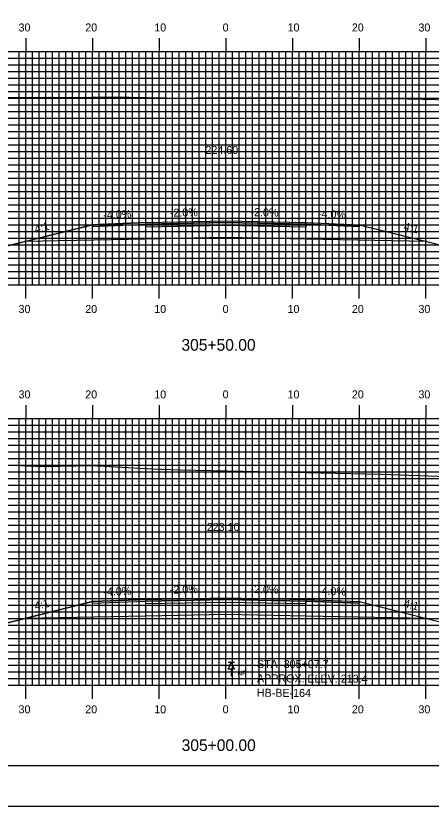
# Model space of a CAD drawing. Extents: x 1816883 to 1817226, y 442591 to 442811.
# Drawn here: x 1817017.1 to 1817079.4, y 442590.5 to 442709 of the extents above; entities that cross this region are included whole.
import ezdxf

# ---------------------------------------------------------------- set-up
doc = ezdxf.new("R2010")
doc.units = 0
for name, color, linetype in [('ANNOTATION', 7, 'Continuous'), ('BORDER', 7, 'Continuous'), ('BORING - NO REFUSAL', 7, 'Continuous'), ('D_Roadway_Centerline', 7, 'Continuous'), ('D_Roadway_Centerline_Text', 7, 'Continuous'), ('D_Roadway_Edge_Shoulder', 7, 'Continuous'), ('D_Roadway_Edge_TW', 7, 'Continuous'), ('D_Roadway_Pavement', 7, 'Continuous'), ('D_Roadway_SlopeLines', 7, 'Continuous'), ('D_Roadway_SubGrade', 7, 'Continuous'), ('H_V ANNOTATION', 7, 'Continuous'), ('MAJOR', 7, 'Continuous'), ('MINOR', 7, 'Continuous'), ('PLOT BOUNDARY', 7, 'Continuous'), ('S_Roadway_Centerline', 7, 'Continuous')]:
    doc.layers.add(name, color=color, linetype=linetype)

msp = doc.modelspace()

# ---------------------------------------------------------------- linework, layer by layer
at = {"layer": 'BORDER'}
msp.add_lwpolyline([(1816898.99, 442596.67), (1817218.99, 442596.67), (1817218.99, 442806.67), (1816898.99, 442806.67)], close=True, dxfattribs=at)
at = {"layer": 'BORING - NO REFUSAL'}
for p, q in [((1817049.87, 442612.07), (1817048.91, 442612.07)), ((1817049.39, 442611.11), (1817049.39, 442610.05))]:
    msp.add_line(p, q, dxfattribs=at)
msp.add_lwpolyline([(1817049.39, 442612.07), (1817049.87, 442611.11), (1817048.91, 442611.11)], close=True, dxfattribs=at)
at = {"layer": 'D_Roadway_Centerline'}
for points in [[(1816958.59, 442696.64), (1816959.84, 442696.56), (1816961.09, 442696.31), (1816962.34, 442695.92), (1816963.59, 442695.37), (1816998.81, 442677.76), (1817003.78, 442677.71), (1817014.41, 442674.17), (1817018.41, 442675.17), (1817028.59, 442677.71), (1817036.59, 442678.03), (1817048.59, 442678.27), (1817060.59, 442678.03), (1817068.59, 442677.71), (1817078.76, 442675.17), (1817082.76, 442674.17), (1817093.39, 442677.71), (1817101.65, 442677.79), (1817133.59, 442693.76), (1817134.84, 442694.3), (1817136.09, 442694.68), (1817137.34, 442694.88), (1817138.59, 442694.92)], [(1816958.59, 442642.2), (1816959.84, 442642.08), (1816961.09, 442641.81), (1816962.34, 442641.41), (1816963.59, 442640.85), (1817002.86, 442621.22), (1817003.78, 442621.21), (1817014.41, 442617.67), (1817018.41, 442618.67), (1817028.59, 442621.21), (1817036.59, 442621.53), (1817048.59, 442621.77), (1817060.59, 442621.53), (1817068.59, 442621.21), (1817078.76, 442618.67), (1817082.76, 442617.67), (1817093.39, 442621.21), (1817102.53, 442621.3), (1817133.59, 442636.83), (1817134.84, 442637.37), (1817136.09, 442637.72), (1817137.34, 442637.9), (1817138.59, 442637.9)]]:
    msp.add_lwpolyline(points, dxfattribs=at)
at = {"layer": 'D_Roadway_Edge_Shoulder'}
for points in [[(1817036.59, 442678.03), (1817028.59, 442677.71), (1817028.59, 442677.46), (1817036.59, 442677.78)], [(1817060.59, 442678.03), (1817068.59, 442677.71), (1817068.59, 442677.46), (1817060.59, 442677.78)], [(1817036.59, 442621.53), (1817028.59, 442621.21), (1817028.59, 442620.96), (1817036.59, 442621.28)], [(1817060.59, 442621.53), (1817068.59, 442621.21), (1817068.59, 442620.96), (1817060.59, 442621.28)]]:
    msp.add_lwpolyline(points, close=True, dxfattribs=at)
at = {"layer": 'D_Roadway_Edge_TW'}
for points in [[(1817036.59, 442677.78), (1817036.59, 442678.03), (1817048.59, 442678.27), (1817060.59, 442678.03), (1817060.59, 442677.78), (1817048.59, 442678.02)], [(1817036.59, 442621.28), (1817036.59, 442621.53), (1817048.59, 442621.77), (1817060.59, 442621.53), (1817060.59, 442621.28), (1817048.59, 442621.52)]]:
    msp.add_lwpolyline(points, close=True, dxfattribs=at)
at = {"layer": 'D_Roadway_Pavement'}
for points in [[(1817036.59, 442677.36), (1817036.59, 442677.78), (1817048.59, 442678.02), (1817060.59, 442677.78), (1817060.59, 442677.36), (1817048.59, 442677.6)], [(1817036.59, 442620.86), (1817036.59, 442621.28), (1817048.59, 442621.52), (1817060.59, 442621.28), (1817060.59, 442620.86), (1817048.59, 442621.1)]]:
    msp.add_lwpolyline(points, close=True, dxfattribs=at)
at = {"layer": 'D_Roadway_SlopeLines'}
for points in [[(1817028.59, 442677.71), (1817014.41, 442674.17)], [(1817068.59, 442677.71), (1817082.76, 442674.17)], [(1817028.59, 442621.21), (1817014.41, 442617.67)], [(1817068.59, 442621.21), (1817082.76, 442617.67)]]:
    msp.add_lwpolyline(points, dxfattribs=at)
at = {"layer": 'D_Roadway_SubGrade'}
for points in [[(1817036.59, 442675.53), (1817018.41, 442675.17), (1817028.59, 442677.71), (1817028.59, 442677.46), (1817036.59, 442677.78), (1817048.59, 442678.02), (1817060.59, 442677.78), (1817068.59, 442677.46), (1817068.59, 442677.71), (1817078.76, 442675.17), (1817060.59, 442675.53), (1817048.59, 442675.77)], [(1817036.59, 442619.03), (1817018.41, 442618.67), (1817028.59, 442621.21), (1817028.59, 442620.96), (1817036.59, 442621.28), (1817048.59, 442621.52), (1817060.59, 442621.28), (1817068.59, 442620.96), (1817068.59, 442621.21), (1817078.76, 442618.67), (1817060.59, 442619.03), (1817048.59, 442619.27)]]:
    msp.add_lwpolyline(points, close=True, dxfattribs=at)
at = {"layer": 'MAJOR'}
for p, q in [((1817018.59, 442705.67), (1817018.59, 442703.67)), ((1817028.59, 442705.67), (1817028.59, 442703.67)), ((1817038.59, 442705.67), (1817038.59, 442703.67)), ((1817048.59, 442705.67), (1817048.59, 442703.67)), ((1817058.59, 442705.67), (1817058.59, 442703.67)), ((1817068.59, 442705.67), (1817068.59, 442703.67)), ((1817078.59, 442705.67), (1817078.59, 442703.67)), ((1816908.59, 442703.67), (1817188.59, 442703.67)), ((1816908.59, 442703.67), (1817188.59, 442703.67)), ((1817018.59, 442668.67), (1817018.59, 442703.67)), ((1817028.59, 442668.67), (1817028.59, 442703.67)), ((1817038.59, 442668.67), (1817038.59, 442703.67)), ((1817048.59, 442668.67), (1817048.59, 442703.67)), ((1817058.59, 442668.67), (1817058.59, 442703.67)), ((1817068.59, 442668.67), (1817068.59, 442703.67)), ((1817078.59, 442668.67), (1817078.59, 442703.67)), ((1816908.59, 442698.67), (1817188.59, 442698.67)), ((1816908.59, 442693.67), (1817188.59, 442693.67)), ((1816908.59, 442688.67), (1817188.59, 442688.67)), ((1816908.59, 442683.67), (1817188.59, 442683.67)), ((1816908.59, 442678.67), (1817188.59, 442678.67)), ((1816908.59, 442673.67), (1817188.59, 442673.67)), ((1816908.59, 442668.67), (1817188.59, 442668.67)), ((1816908.59, 442668.67), (1817188.59, 442668.67)), ((1817018.59, 442666.66), (1817018.59, 442668.67)), ((1817028.59, 442666.66), (1817028.59, 442668.67)), ((1817038.59, 442666.66), (1817038.59, 442668.67)), ((1817048.59, 442666.66), (1817048.59, 442668.67)), ((1817058.59, 442666.66), (1817058.59, 442668.67)), ((1817068.59, 442666.66), (1817068.59, 442668.67)), ((1817078.59, 442666.66), (1817078.59, 442668.67)), ((1817018.59, 442650.67), (1817018.59, 442648.67)), ((1817028.59, 442650.67), (1817028.59, 442648.67)), ((1817038.59, 442650.67), (1817038.59, 442648.67)), ((1817048.59, 442650.67), (1817048.59, 442648.67)), ((1817058.59, 442650.67), (1817058.59, 442648.67)), ((1817068.59, 442650.67), (1817068.59, 442648.67)), ((1817078.59, 442650.67), (1817078.59, 442648.67)), ((1816908.59, 442648.67), (1817188.59, 442648.67)), ((1816908.59, 442648.67), (1817188.59, 442648.67)), ((1817018.59, 442608.67), (1817018.59, 442648.67)), ((1817028.59, 442608.67), (1817028.59, 442648.67)), ((1817038.59, 442608.67), (1817038.59, 442648.67)), ((1817048.59, 442608.67), (1817048.59, 442648.67)), ((1817058.59, 442608.67), (1817058.59, 442648.67)), ((1817068.59, 442608.67), (1817068.59, 442648.67)), ((1817078.59, 442608.67), (1817078.59, 442648.67)), ((1816908.59, 442643.67), (1817188.59, 442643.67)), ((1816908.59, 442638.67), (1817188.59, 442638.67)), ((1816908.59, 442633.67), (1817188.59, 442633.67)), ((1816908.59, 442628.67), (1817188.59, 442628.67)), ((1816908.59, 442623.67), (1817188.59, 442623.67)), ((1816908.59, 442618.67), (1817188.59, 442618.67)), ((1816908.59, 442613.67), (1817188.59, 442613.67)), ((1816908.59, 442608.67), (1817188.59, 442608.67)), ((1816908.59, 442608.67), (1817188.59, 442608.67)), ((1817018.59, 442606.66), (1817018.59, 442608.67)), ((1817028.59, 442606.66), (1817028.59, 442608.67)), ((1817038.59, 442606.66), (1817038.59, 442608.67)), ((1817048.59, 442606.66), (1817048.59, 442608.67)), ((1817058.59, 442606.66), (1817058.59, 442608.67)), ((1817068.59, 442606.66), (1817068.59, 442608.67)), ((1817078.59, 442606.66), (1817078.59, 442608.67))]:
    msp.add_line(p, q, dxfattribs=at)
at = {"layer": 'MINOR'}
for p, q in [((1817017.59, 442668.67), (1817017.59, 442703.67)), ((1817019.59, 442668.67), (1817019.59, 442703.67)), ((1817020.59, 442668.67), (1817020.59, 442703.67)), ((1817021.59, 442668.67), (1817021.59, 442703.67)), ((1817022.59, 442668.67), (1817022.59, 442703.67)), ((1817023.59, 442668.67), (1817023.59, 442703.67)), ((1817024.59, 442668.67), (1817024.59, 442703.67)), ((1817025.59, 442668.67), (1817025.59, 442703.67)), ((1817026.59, 442668.67), (1817026.59, 442703.67)), ((1817027.59, 442668.67), (1817027.59, 442703.67)), ((1817029.59, 442668.67), (1817029.59, 442703.67)), ((1817030.59, 442668.67), (1817030.59, 442703.67)), ((1817031.59, 442668.67), (1817031.59, 442703.67)), ((1817032.59, 442668.67), (1817032.59, 442703.67)), ((1817033.59, 442668.67), (1817033.59, 442703.67)), ((1817034.59, 442668.67), (1817034.59, 442703.67)), ((1817035.59, 442668.67), (1817035.59, 442703.67)), ((1817036.59, 442668.67), (1817036.59, 442703.67)), ((1817037.59, 442668.67), (1817037.59, 442703.67)), ((1817039.59, 442668.67), (1817039.59, 442703.67)), ((1817040.59, 442668.67), (1817040.59, 442703.67)), ((1817041.59, 442668.67), (1817041.59, 442703.67)), ((1817042.59, 442668.67), (1817042.59, 442703.67)), ((1817043.59, 442668.67), (1817043.59, 442703.67)), ((1817044.59, 442668.67), (1817044.59, 442703.67)), ((1817045.59, 442668.67), (1817045.59, 442703.67)), ((1817046.59, 442668.67), (1817046.59, 442703.67)), ((1817047.59, 442668.67), (1817047.59, 442703.67)), ((1817049.59, 442668.67), (1817049.59, 442703.67)), ((1817050.59, 442668.67), (1817050.59, 442703.67)), ((1817051.59, 442668.67), (1817051.59, 442703.67)), ((1817052.59, 442668.67), (1817052.59, 442703.67)), ((1817053.59, 442668.67), (1817053.59, 442703.67)), ((1817054.59, 442668.67), (1817054.59, 442703.67)), ((1817055.59, 442668.67), (1817055.59, 442703.67)), ((1817056.59, 442668.67), (1817056.59, 442703.67)), ((1817057.59, 442668.67), (1817057.59, 442703.67)), ((1817059.59, 442668.67), (1817059.59, 442703.67)), ((1817060.59, 442668.67), (1817060.59, 442703.67)), ((1817061.59, 442668.67), (1817061.59, 442703.67)), ((1817062.59, 442668.67), (1817062.59, 442703.67)), ((1817063.59, 442668.67), (1817063.59, 442703.67)), ((1817064.59, 442668.67), (1817064.59, 442703.67)), ((1817065.59, 442668.67), (1817065.59, 442703.67)), ((1817066.59, 442668.67), (1817066.59, 442703.67)), ((1817067.59, 442668.67), (1817067.59, 442703.67)), ((1817069.59, 442668.67), (1817069.59, 442703.67)), ((1817070.59, 442668.67), (1817070.59, 442703.67)), ((1817071.59, 442668.67), (1817071.59, 442703.67)), ((1817072.59, 442668.67), (1817072.59, 442703.67)), ((1817073.59, 442668.67), (1817073.59, 442703.67)), ((1817074.59, 442668.67), (1817074.59, 442703.67)), ((1817075.59, 442668.67), (1817075.59, 442703.67)), ((1817076.59, 442668.67), (1817076.59, 442703.67)), ((1817077.59, 442668.67), (1817077.59, 442703.67)), ((1816908.59, 442702.67), (1817188.59, 442702.67)), ((1816908.59, 442701.67), (1817188.59, 442701.67)), ((1816908.59, 442700.67), (1817188.59, 442700.67)), ((1816908.59, 442699.67), (1817188.59, 442699.67)), ((1816908.59, 442697.67), (1817188.59, 442697.67)), ((1816908.59, 442696.67), (1817188.59, 442696.67)), ((1816908.59, 442695.67), (1817188.59, 442695.67)), ((1816908.59, 442694.67), (1817188.59, 442694.67)), ((1816908.59, 442692.67), (1817188.59, 442692.67)), ((1816908.59, 442691.67), (1817188.59, 442691.67)), ((1816908.59, 442690.67), (1817188.59, 442690.67)), ((1816908.59, 442689.67), (1817188.59, 442689.67)), ((1816908.59, 442687.67), (1817188.59, 442687.67)), ((1816908.59, 442686.67), (1817188.59, 442686.67)), ((1816908.59, 442685.67), (1817188.59, 442685.67)), ((1816908.59, 442684.67), (1817188.59, 442684.67)), ((1816908.59, 442682.67), (1817188.59, 442682.67)), ((1816908.59, 442681.67), (1817188.59, 442681.67)), ((1816908.59, 442680.67), (1817188.59, 442680.67)), ((1816908.59, 442679.67), (1817188.59, 442679.67)), ((1816908.59, 442677.67), (1817188.59, 442677.67)), ((1816908.59, 442676.67), (1817188.59, 442676.67)), ((1816908.59, 442675.67), (1817188.59, 442675.67)), ((1816908.59, 442674.67), (1817188.59, 442674.67)), ((1816908.59, 442672.67), (1817188.59, 442672.67)), ((1816908.59, 442671.67), (1817188.59, 442671.67)), ((1816908.59, 442670.67), (1817188.59, 442670.67)), ((1816908.59, 442669.67), (1817188.59, 442669.67)), ((1816908.59, 442647.67), (1817188.59, 442647.67)), ((1817017.59, 442608.67), (1817017.59, 442648.67)), ((1817019.59, 442608.67), (1817019.59, 442648.67)), ((1817020.59, 442608.67), (1817020.59, 442648.67)), ((1817021.59, 442608.67), (1817021.59, 442648.67)), ((1817022.59, 442608.67), (1817022.59, 442648.67)), ((1817023.59, 442608.67), (1817023.59, 442648.67)), ((1817024.59, 442608.67), (1817024.59, 442648.67)), ((1817025.59, 442608.67), (1817025.59, 442648.67)), ((1817026.59, 442608.67), (1817026.59, 442648.67)), ((1817027.59, 442608.67), (1817027.59, 442648.67)), ((1817029.59, 442608.67), (1817029.59, 442648.67)), ((1817030.59, 442608.67), (1817030.59, 442648.67)), ((1817031.59, 442608.67), (1817031.59, 442648.67)), ((1817032.59, 442608.67), (1817032.59, 442648.67)), ((1817033.59, 442608.67), (1817033.59, 442648.67)), ((1817034.59, 442608.67), (1817034.59, 442648.67)), ((1817035.59, 442608.67), (1817035.59, 442648.67)), ((1817036.59, 442608.67), (1817036.59, 442648.67)), ((1817037.59, 442608.67), (1817037.59, 442648.67)), ((1817039.59, 442608.67), (1817039.59, 442648.67)), ((1817040.59, 442608.67), (1817040.59, 442648.67)), ((1817041.59, 442608.67), (1817041.59, 442648.67)), ((1817042.59, 442608.67), (1817042.59, 442648.67)), ((1817043.59, 442608.67), (1817043.59, 442648.67)), ((1817044.59, 442608.67), (1817044.59, 442648.67)), ((1817045.59, 442608.67), (1817045.59, 442648.67)), ((1817046.59, 442608.67), (1817046.59, 442648.67)), ((1817047.59, 442608.67), (1817047.59, 442648.67)), ((1817049.59, 442608.67), (1817049.59, 442648.67)), ((1817050.59, 442608.67), (1817050.59, 442648.67)), ((1817051.59, 442608.67), (1817051.59, 442648.67)), ((1817052.59, 442608.67), (1817052.59, 442648.67)), ((1817053.59, 442608.67), (1817053.59, 442648.67)), ((1817054.59, 442608.67), (1817054.59, 442648.67)), ((1817055.59, 442608.67), (1817055.59, 442648.67)), ((1817056.59, 442608.67), (1817056.59, 442648.67)), ((1817057.59, 442608.67), (1817057.59, 442648.67)), ((1817059.59, 442608.67), (1817059.59, 442648.67)), ((1817060.59, 442608.67), (1817060.59, 442648.67)), ((1817061.59, 442608.67), (1817061.59, 442648.67)), ((1817062.59, 442608.67), (1817062.59, 442648.67)), ((1817063.59, 442608.67), (1817063.59, 442648.67)), ((1817064.59, 442608.67), (1817064.59, 442648.67)), ((1817065.59, 442608.67), (1817065.59, 442648.67)), ((1817066.59, 442608.67), (1817066.59, 442648.67)), ((1817067.59, 442608.67), (1817067.59, 442648.67)), ((1817069.59, 442608.67), (1817069.59, 442648.67)), ((1817070.59, 442608.67), (1817070.59, 442648.67)), ((1817071.59, 442608.67), (1817071.59, 442648.67)), ((1817072.59, 442608.67), (1817072.59, 442648.67)), ((1817073.59, 442608.67), (1817073.59, 442648.67)), ((1817074.59, 442608.67), (1817074.59, 442648.67)), ((1817075.59, 442608.67), (1817075.59, 442648.67)), ((1817076.59, 442608.67), (1817076.59, 442648.67)), ((1817077.59, 442608.67), (1817077.59, 442648.67)), ((1816908.59, 442646.67), (1817188.59, 442646.67)), ((1816908.59, 442645.67), (1817188.59, 442645.67)), ((1816908.59, 442644.67), (1817188.59, 442644.67)), ((1816908.59, 442642.67), (1817188.59, 442642.67)), ((1816908.59, 442641.67), (1817188.59, 442641.67)), ((1816908.59, 442640.67), (1817188.59, 442640.67)), ((1816908.59, 442639.67), (1817188.59, 442639.67)), ((1816908.59, 442637.67), (1817188.59, 442637.67)), ((1816908.59, 442636.67), (1817188.59, 442636.67)), ((1816908.59, 442635.67), (1817188.59, 442635.67)), ((1816908.59, 442634.67), (1817188.59, 442634.67)), ((1816908.59, 442632.67), (1817188.59, 442632.67)), ((1816908.59, 442631.67), (1817188.59, 442631.67)), ((1816908.59, 442630.67), (1817188.59, 442630.67)), ((1816908.59, 442629.67), (1817188.59, 442629.67)), ((1816908.59, 442627.67), (1817188.59, 442627.67)), ((1816908.59, 442626.67), (1817188.59, 442626.67)), ((1816908.59, 442625.67), (1817188.59, 442625.67)), ((1816908.59, 442624.67), (1817188.59, 442624.67)), ((1816908.59, 442622.67), (1817188.59, 442622.67)), ((1816908.59, 442621.67), (1817188.59, 442621.67)), ((1816908.59, 442620.67), (1817188.59, 442620.67)), ((1816908.59, 442619.67), (1817188.59, 442619.67)), ((1816908.59, 442617.67), (1817188.59, 442617.67)), ((1816908.59, 442616.67), (1817188.59, 442616.67)), ((1816908.59, 442615.67), (1817188.59, 442615.67)), ((1816908.59, 442614.67), (1817188.59, 442614.67)), ((1816908.59, 442612.67), (1817188.59, 442612.67)), ((1816908.59, 442611.67), (1817188.59, 442611.67)), ((1816908.59, 442610.67), (1817188.59, 442610.67)), ((1816908.59, 442609.67), (1817188.59, 442609.67))]:
    msp.add_line(p, q, dxfattribs=at)
at = {"layer": 'PLOT BOUNDARY'}
msp.add_lwpolyline([(1816882.8, 442590.55), (1817222.8, 442590.55), (1817222.8, 442810.55), (1816882.8, 442810.55)], close=True, dxfattribs=at)
at = {"layer": 'S_Roadway_Centerline'}
for points in [[(1816945.61, 442696.57), (1816957.82, 442696.65), (1816963.42, 442696.6), (1816974.67, 442696.49), (1816986.19, 442696.98), (1816991.48, 442697.18), (1817003.59, 442696.66), (1817008.75, 442696.73), (1817017.48, 442696.83), (1817025.38, 442696.78), (1817031.42, 442696.85), (1817042.12, 442696.69), (1817044.01, 442696.7), (1817052.76, 442696.7), (1817058.07, 442696.71), (1817059.32, 442696.73), (1817061.28, 442696.69), (1817075.83, 442696.56), (1817084.59, 442696.39)], [(1816954.65, 442642.34), (1816962.57, 442642.05), (1816970.49, 442642.14), (1816974.39, 442642.2), (1816988.01, 442642.17), (1816988.23, 442642.17), (1816989.11, 442642.17), (1817004.56, 442642.05), (1817009.66, 442641.92), (1817021.34, 442641.44), (1817028.42, 442641.62), (1817037.57, 442641.09), (1817041.73, 442640.97), (1817055.84, 442640.66), (1817055.88, 442640.66), (1817056.03, 442640.66), (1817071.91, 442640.29), (1817081.78, 442639.98)]]:
    msp.add_lwpolyline(points, dxfattribs=at)

# ---------------------------------------------------------------- texts
at = {"layer": 'ANNOTATION'}
for s, rotation, p in [('-4.0%', 2.2906, (1817030.22, 442678.58)), ('-2.0%', 1.1458, (1817040.19, 442678.9)), ('-2.0%', 358.8542, (1817052.27, 442679)), ('-4.0%', 357.7094, (1817062.38, 442678.76)), ('4:1', 14.0362, (1817020.03, 442676.43)), ('4:1', 345.9638, (1817075.18, 442676.92)), ('-4.0%', 2.2906, (1817030.22, 442622.08)), ('-2.0%', 1.1458, (1817040.19, 442622.4)), ('-2.0%', 358.8542, (1817052.27, 442622.5)), ('-4.0%', 357.7094, (1817062.38, 442622.26)), ('4:1', 14.0362, (1817020.03, 442619.93)), ('4:1', 345.9638, (1817075.18, 442620.42))]:
    msp.add_text(s, height=1.2, rotation=rotation, dxfattribs=at).set_placement(p)
at = {"layer": 'BORING - NO REFUSAL'}
for s, p in [('STA. 305+07.7', (1817053.25, 442611.27)), ('APPROX. ELEV. 213.4', (1817053.25, 442609.11)), ('HB-BE-164', (1817053.24, 442606.95))]:
    msp.add_text(s, height=1.2, rotation=359.8142, dxfattribs=at).set_placement(p)
msp.add_text('NR', height=0.7, dxfattribs=at).set_placement((1817050.32, 442610.15))
at = {"layer": 'D_Roadway_Centerline'}
for s, p in [('C', (1817048.58, 442678.27)), ('L', (1817048.59, 442678.26)), ('C', (1817048.58, 442621.77)), ('L', (1817048.59, 442621.76))]:
    msp.add_text(s, height=0.0146, dxfattribs=at).set_placement(p)
at = {"layer": 'D_Roadway_Centerline_Text'}
for s, p in [('224.60', (1817045.53, 442688.3)), ('223.10', (1817045.73, 442631.8))]:
    msp.add_text(s, height=1.2, dxfattribs=at).set_placement(p)
at = {"layer": 'H_V ANNOTATION'}
for s, height, p in [('30', 1.2, (1817017.48, 442706.67)), ('20', 1.2, (1817027.49, 442706.67)), ('10', 1.2, (1817037.84, 442706.67)), ('0', 1.2, (1817048.1, 442706.67)), ('10', 1.2, (1817057.84, 442706.67)), ('20', 1.2, (1817067.49, 442706.67)), ('30', 1.2, (1817077.48, 442706.67)), ('30', 1.2, (1817017.48, 442664.47)), ('20', 1.2, (1817027.49, 442664.47)), ('10', 1.2, (1817037.84, 442664.47)), ('0', 1.2, (1817048.1, 442664.47)), ('10', 1.2, (1817057.84, 442664.47)), ('20', 1.2, (1817067.49, 442664.47)), ('30', 1.2, (1817077.48, 442664.47)), ('305+50.00', 1.75, (1817041.92, 442658.82)), ('30', 1.2, (1817017.48, 442651.67)), ('20', 1.2, (1817027.49, 442651.67)), ('10', 1.2, (1817037.84, 442651.67)), ('0', 1.2, (1817048.1, 442651.67)), ('10', 1.2, (1817057.84, 442651.67)), ('20', 1.2, (1817067.49, 442651.67)), ('30', 1.2, (1817077.48, 442651.67)), ('30', 1.2, (1817017.48, 442604.47)), ('20', 1.2, (1817027.49, 442604.47)), ('10', 1.2, (1817037.84, 442604.47)), ('0', 1.2, (1817048.1, 442604.47)), ('10', 1.2, (1817057.84, 442604.47)), ('20', 1.2, (1817067.49, 442604.47)), ('30', 1.2, (1817077.48, 442604.47)), ('305+00.00', 1.75, (1817041.95, 442598.82))]:
    msp.add_text(s, height=height, dxfattribs=at).set_placement(p)

doc.saveas('drawing.dxf')
